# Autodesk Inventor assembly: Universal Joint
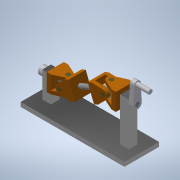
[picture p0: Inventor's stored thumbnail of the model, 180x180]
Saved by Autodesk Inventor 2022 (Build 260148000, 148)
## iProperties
Created: 2014-03
Part Number: Universal Joint
Document SubType Name: Assembly
Designer: John
Author: John
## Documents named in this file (8)
- C:\Users\helfenj\Desktop\Ex_Files_Autodesk_Inventor_2022_Essential_Training\Exercise Files\11_Adding parts to an assembly file\11_03\Universal Joint.iam
- C:\Users\helfenj\Desktop\Ex_Files_Autodesk_Inventor_2022_Essential_Training\Exercise Files\11_Adding parts to an assembly file\11_03\base.ipt
- C:\Users\helfenj\Desktop\Ex_Files_Autodesk_Inventor_2022_Essential_Training\Exercise Files\11_Adding parts to an assembly file\11_03\Connector.ipt
- C:\Users\helfenj\Desktop\Ex_Files_Autodesk_Inventor_2022_Essential_Training\Exercise Files\11_Adding parts to an assembly file\11_03\Joint.ipt
- C:\Users\helfenj\Desktop\Ex_Files_Autodesk_Inventor_2022_Essential_Training\Exercise Files\11_Adding parts to an assembly file\11_03\Connecting Rod.ipt
- C:\Users\helfenj\Desktop\Ex_Files_Autodesk_Inventor_2022_Essential_Training\Exercise Files\11_Adding parts to an assembly file\11_03\Crank Rod.ipt
- C:\Users\helfenj\Desktop\Ex_Files_Autodesk_Inventor_2022_Essential_Training\Exercise Files\11_Adding parts to an assembly file\11_03\Crank Handle.ipt
- C:\Users\helfenj\Desktop\Ex_Files_Autodesk_Inventor_2022_Essential_Training\Exercise Files\11_Adding parts to an assembly file\11_03\Pin.ipt
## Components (20 placed, 8 different names)
1. base:1 — Mate:1, Mate:2, Mate:9, Mate:10, Mate:15, Mate:16, Angle:3 - DRIVE THIS
2. Connector:1 — Mate:3, Mate:4, Mate:7, Mate:8
3. Connector:2 — Mate:5, Mate:6, Mate:11, Mate:12
4. Joint:1 — Mate:1, Mate:2, Mate:3, Mate:4, Flush:3, Angle:1, Insert:1, Insert:2
5. Joint:2 — Mate:5, Mate:6, Mate:9, Mate:10, Flush:4, Angle:2, Insert:5, Insert:8
6. Joint:3 — Mate:7, Mate:8, Mate:13, Flush:1, Mate:14, Insert:3, Insert:4
7. Joint:4 — Mate:11, Mate:12, Mate:13, Flush:1, Flush:2, Insert:6, Insert:7
8. Connecting Rod:1 — Mate:14, Flush:2
9. Crank Rod:1 — Mate:15, Flush:3, Flush:5, Mate:17
10. Crank Rod:2 — Flush:4, Mate:16, Flush:6, Mate:18
11. Crank Handle:1 - DRIVE — Flush:5, Mate:17, Angle:1, Angle:3 - DRIVE THIS
12. Crank Handle:2 — Flush:6, Angle:2, Mate:18
13. Pin:1 — Insert:1
14. Pin:2 — Insert:4
15. Pin:3 — Insert:3
16. Pin:4 — Insert:2
17. Pin:5 — Insert:7
18. Pin:6 — Insert:8
19. Pin:7 — Insert:6
20. Pin:8 — Insert:5
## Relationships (35: Mate 18, Insert 8, Flush 6, Angle 3)
- Mate:1: base:1 ↔ Joint:1
- Mate:2: base:1 ↔ Joint:1
- Mate:3: Connector:1 ↔ Joint:1
- Mate:4: Connector:1 ↔ Joint:1
- Mate:5: Connector:2 ↔ Joint:2
- Mate:6: Connector:2 ↔ Joint:2
- Mate:7: Connector:1 ↔ Joint:3
- Mate:8: Connector:1 ↔ Joint:3
- Mate:9: base:1 ↔ Joint:2
- Mate:10: base:1 ↔ Joint:2
- Mate:11: Connector:2 ↔ Joint:4
- Mate:12: Connector:2 ↔ Joint:4
- Mate:13: Joint:3 ↔ Joint:4
- Flush:1: Joint:3 ↔ Joint:4
- Mate:14: Joint:3 ↔ Connecting Rod:1
- Flush:2: Joint:4 ↔ Connecting Rod:1
- Mate:15: base:1 ↔ Crank Rod:1
- Flush:3: Joint:1 ↔ Crank Rod:1
- Flush:4: Joint:2 ↔ Crank Rod:2
- Mate:16: base:1 ↔ Crank Rod:2
- Flush:5: Crank Rod:1 ↔ Crank Handle:1 - DRIVE
- Mate:17: Crank Rod:1 ↔ Crank Handle:1 - DRIVE
- Angle:1: Joint:1 ↔ Crank Handle:1 - DRIVE
- Flush:6: Crank Rod:2 ↔ Crank Handle:2
- Angle:2: Joint:2 ↔ Crank Handle:2
- Mate:18: Crank Rod:2 ↔ Crank Handle:2
- Insert:1: Joint:1 ↔ Pin:1
- Insert:2: Joint:1 ↔ Pin:4
- Insert:3: Joint:3 ↔ Pin:3
- Insert:4: Joint:3 ↔ Pin:2
- Insert:5: Joint:2 ↔ Pin:8
- Insert:6: Joint:4 ↔ Pin:7
- Insert:7: Joint:4 ↔ Pin:5
- Insert:8: Joint:2 ↔ Pin:6
- Angle:3 - DRIVE THIS: base:1 ↔ Crank Handle:1 - DRIVE
